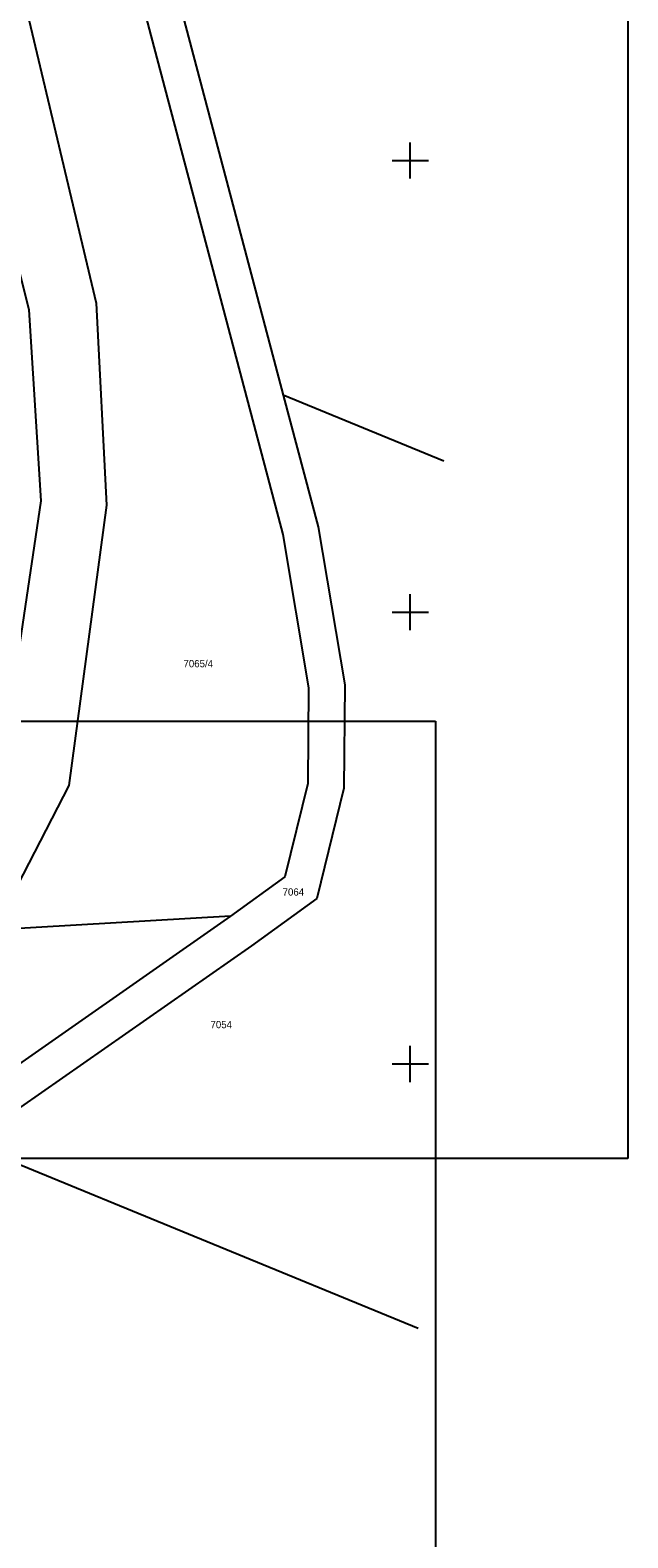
# Model space of a CAD drawing. Extents: x -612546 to -611926, y -1201932 to -1200444.
# Drawn here: x -611992.1 to -611925.9, y -1201602.4 to -1201435.6 of the extents above; entities that cross this region are included whole.
import ezdxf

# ---------------------------------------------------------------- set-up
doc = ezdxf.new("R2010")
doc.units = 0
for name, color, linetype in [('61 legenda křížky', 7, 'Continuous'), ('Hranice parcel', 7, 'Continuous'), ('Parcelní čísla', 7, 'Continuous'), ('Vnitřní kresba', 7, 'Continuous'), ('Vrstva 63', 7, 'Continuous')]:
    doc.layers.add(name, color=color, linetype=linetype)

msp = doc.modelspace()

# ---------------------------------------------------------------- linework, layer by layer
at = {"layer": '61 legenda křížky'}
for p, q in [((-611950, -1201452), (-611950, -1201448)), ((-611952, -1201450), (-611948, -1201450)), ((-611950, -1201502), (-611950, -1201498)), ((-611952, -1201500), (-611948, -1201500)), ((-611950, -1201552), (-611950, -1201548)), ((-611952, -1201550), (-611948, -1201550))]:
    msp.add_line(p, q, dxfattribs=at)
at = {"layer": 'Hranice parcel'}
for p, q in [((-611946.28, -1201483.27), (-611964.05, -1201475.97)), ((-611969.89, -1201533.65), (-611996.06, -1201535.15)), ((-611949.12, -1201579.28), (-611998.56, -1201558.96))]:
    msp.add_line(p, q, dxfattribs=at)
for points in [[(-611965.41, -1201269.18), (-611978.05, -1201272.7), (-611982.14, -1201277.79), (-611991.69, -1201317.67), (-611985.19, -1201395.99), (-611964.05, -1201475.97)], [(-612009.76, -1201369.19), (-611997.24, -1201413.36), (-611984.77, -1201465.78), (-611983.62, -1201488.16), (-611987.79, -1201519.18), (-611996.06, -1201535.15)], [(-611989.14, -1201396.64), (-611964.11, -1201491.41), (-611961.25, -1201508.35), (-611961.35, -1201518.96), (-611963.88, -1201529.3), (-611969.89, -1201533.65)], [(-611964.05, -1201475.97), (-611960.2, -1201490.55), (-611957.25, -1201508.03), (-611957.35, -1201519.46), (-611960.34, -1201531.68), (-611967.57, -1201536.91), (-611995.49, -1201556.41), (-611998.56, -1201558.96)], [(-611969.89, -1201533.65), (-611997.92, -1201553.23), (-612006.98, -1201560.76), (-612020.6, -1201579.7), (-612029.6, -1201596.32), (-612036.2, -1201613.55), (-612042.99, -1201636.89), (-612045.15, -1201648.68)]]:
    msp.add_lwpolyline(points, dxfattribs=at)
at = {"layer": 'Vnitřní kresba'}
msp.add_lwpolyline([(-612167.45, -1201850.95), (-612159.31, -1201839.87), (-612135.2, -1201807.83), (-612099.97, -1201758.55), (-612082.71, -1201730.21), (-612068.43, -1201702.85), (-612066.16, -1201687.46), (-612066.16, -1201656.85), (-612064.63, -1201639.3), (-612057.32, -1201615.06), (-612036.83, -1201583.77), (-612007.13, -1201540.95), (-611995.21, -1201517.05), (-611990.85, -1201487.68), (-611992.18, -1201466.53), (-612005.11, -1201415.22), (-612025.88, -1201339.7), (-612042.61, -1201277.13), (-612043.67, -1201266.17)], dxfattribs=at)
at = {"layer": 'Vrstva 63'}
for p, q in [((-611925.92, -1201140.45), (-611925.92, -1201560.45)), ((-612244.2, -1201512.06), (-611947.2, -1201512.06)), ((-611947.2, -1201512.06), (-611947.2, -1201932.06)), ((-611925.92, -1201560.45), (-612222.92, -1201560.45))]:
    msp.add_line(p, q, dxfattribs=at)

# ---------------------------------------------------------------- texts
at = {"layer": 'Parcelní čísla'}
for s, p in [('7065/4', (-611975.1, -1201506.09)), ('7064', (-611964.13, -1201531.36)), ('7054', (-611972.11, -1201546.04))]:
    msp.add_text(s, height=0.8, dxfattribs=at).set_placement(p)

doc.saveas('drawing.dxf')
